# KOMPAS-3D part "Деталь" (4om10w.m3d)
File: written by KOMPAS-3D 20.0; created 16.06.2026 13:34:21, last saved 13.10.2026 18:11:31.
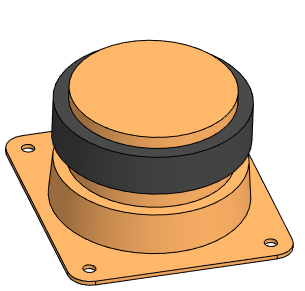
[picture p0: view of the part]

Document properties: Полное имя файла: D:\RicWork\Project-EPS32\box_compas\динамик\4om10w.m3d

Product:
- Part/product: Деталь
    Масса: 0.317349

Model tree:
1. Эскиз:1
2. Элемент выдавливания:1
     Расстояние 1 = 1
3. Эскиз:2  (with: Элемент выдавливания:1)
4. Элемент выдавливания:2
     Расстояние 1 = 10; Угол 1 = 4
5. Эскиз:3  (with: Элемент выдавливания:2)
6. Элемент выдавливания:4
     Расстояние 1 = 10
7. Элемент выдавливания:5
     Расстояние 1 = 6
8. Эскиз:4  (with: Элемент выдавливания:5)
9. Элемент выдавливания:6
     Расстояние 1 = 10
10. Эскиз:5  (with: Элемент выдавливания:6)
11. Элемент выдавливания:7
     Расстояние 1 = 3
12. Элемент выдавливания:9  (with: Элемент выдавливания:1)
     Расстояние 1 = 3
13. Элемент выдавливания:10  (with: Элемент выдавливания:1)
     Расстояние 1 = 3
14. Эскиз:7  (with: Элемент выдавливания:1, Элемент выдавливания:9, Элемент выдавливания:10)
15. Элемент выдавливания:11
     Расстояние 2 = 1
16. Скругление:2  (with: Элемент выдавливания:9, Элемент выдавливания:10)
     Радиус = 5
17. Эскиз:8  (with: Элемент выдавливания:1, Элемент выдавливания:7)
18. Элемент выдавливания:12
     Расстояние 2 = 10
19. Эскиз:9  (with: Элемент выдавливания:12)
20. Элемент выдавливания:13
     Расстояние 1 = 10
21. Скругление:3  (with: Элемент выдавливания:13)
     Радиус = 8
22. Эскиз:10  (with: Элемент выдавливания:1, Элемент выдавливания:9, Элемент выдавливания:10, Элемент выдавливания:2)
23. Эскиз:11  (with: Элемент выдавливания:10, Элемент выдавливания:7)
